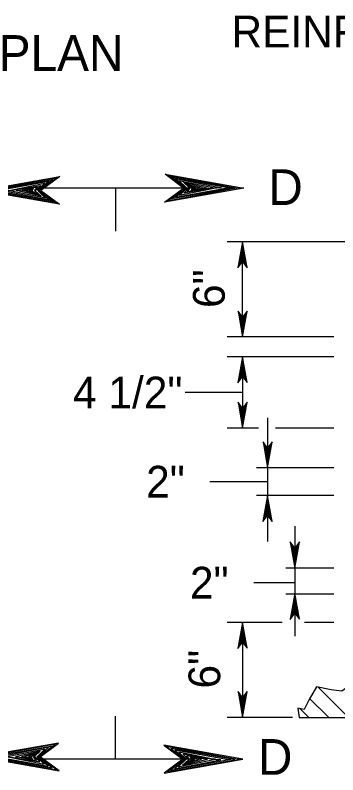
# Model space of a CAD drawing. Extents: x 499866 to 500993, y 499985 to 500645.
# Drawn here: x 500124.8 to 500165.5, y 500455.4 to 500551.1 of the extents above; entities that cross this region are included whole.
import ezdxf

# ---------------------------------------------------------------- set-up
doc = ezdxf.new("R2010")
doc.units = 0
for name, color, linetype in [('2', 7, 'Continuous'), ('24', 7, 'Continuous'), ('5', 7, 'Continuous')]:
    doc.layers.add(name, color=color, linetype=linetype)

msp = doc.modelspace()

# ---------------------------------------------------------------- linework, layer by layer
at = {"layer": '2'}
for p, q in [((500137.466, 500523.851), (500137.466, 500529.295)), ((500137.366, 500462.748), (500137.366, 500457.304))]:
    msp.add_line(p, q, dxfattribs=at)
at = {"layer": '24'}
for points in [[(500153.444, 500522.518), (500152.865, 500519.244), (500153.444, 500520.026), (500154.013, 500519.261), (500153.444, 500522.518), (500153.45, 500522.301), (500152.908, 500519.336), (500153.451, 500520.087), (500153.969, 500519.393), (500153.46, 500522.183), (500153.444, 500522.074), (500152.992, 500519.534), (500153.45, 500520.104), (500153.895, 500519.518), (500153.444, 500522.024), (500153.46, 500521.915), (500153.059, 500519.696), (500153.444, 500520.127), (500153.843, 500519.686), (500153.46, 500521.599), (500153.46, 500521.415), (500153.142, 500519.86), (500153.434, 500520.162), (500153.76, 500519.837), (500153.444, 500521.382), (500153.434, 500521.207), (500153.234, 500520.038), (500153.46, 500520.263), (500153.684, 500520.019), (500153.444, 500521.046), (500153.427, 500520.881), (500153.293, 500520.179), (500153.451, 500520.295), (500153.626, 500520.104), (500153.444, 500520.796), (500153.335, 500520.338), (500153.46, 500520.404), (500153.586, 500520.203), (500153.46, 500520.68), (500153.385, 500520.38), (500153.484, 500520.506), (500153.543, 500520.362), (500153.451, 500520.505), (500153.434, 500520.43)], [(500153.444, 500510.527), (500154.023, 500513.801), (500153.444, 500513.019), (500152.874, 500513.784), (500153.444, 500510.527), (500153.438, 500510.745), (500153.98, 500513.71), (500153.437, 500512.958), (500152.919, 500513.652), (500153.428, 500510.862), (500153.444, 500510.971), (500153.895, 500513.511), (500153.437, 500512.941), (500152.993, 500513.527), (500153.444, 500511.021), (500153.428, 500511.13), (500153.828, 500513.35), (500153.444, 500512.918), (500153.045, 500513.359), (500153.427, 500511.446), (500153.428, 500511.631), (500153.746, 500513.185), (500153.453, 500512.883), (500153.128, 500513.208), (500153.444, 500511.663), (500153.454, 500511.838), (500153.654, 500513.007), (500153.427, 500512.782), (500153.203, 500513.026), (500153.444, 500511.999), (500153.46, 500512.164), (500153.594, 500512.866), (500153.437, 500512.75), (500153.262, 500512.942), (500153.444, 500512.249), (500153.553, 500512.707), (500153.428, 500512.641), (500153.302, 500512.842), (500153.427, 500512.365), (500153.503, 500512.665), (500153.404, 500512.539), (500153.344, 500512.684), (500153.437, 500512.54), (500153.453, 500512.615)], [(500153.444, 500508.029), (500152.865, 500504.755), (500153.444, 500505.537), (500154.013, 500504.772), (500153.444, 500508.029), (500153.45, 500507.812), (500152.908, 500504.846), (500153.451, 500505.598), (500153.969, 500504.904), (500153.46, 500507.694), (500153.444, 500507.585), (500152.992, 500505.045), (500153.45, 500505.615), (500153.895, 500505.029), (500153.444, 500507.535), (500153.46, 500507.427), (500153.059, 500505.206), (500153.444, 500505.638), (500153.843, 500505.198), (500153.46, 500507.11), (500153.46, 500506.926), (500153.142, 500505.371), (500153.434, 500505.673), (500153.76, 500505.348), (500153.444, 500506.893), (500153.434, 500506.718), (500153.234, 500505.549), (500153.46, 500505.774), (500153.684, 500505.53), (500153.444, 500506.557), (500153.427, 500506.392), (500153.293, 500505.69), (500153.451, 500505.806), (500153.626, 500505.615), (500153.444, 500506.307), (500153.335, 500505.849), (500153.46, 500505.915), (500153.586, 500505.714), (500153.46, 500506.192), (500153.385, 500505.891), (500153.484, 500506.017), (500153.543, 500505.873), (500153.451, 500506.016), (500153.434, 500505.941)], [(500153.444, 500499.036), (500154.023, 500502.31), (500153.444, 500501.528), (500152.874, 500502.293), (500153.444, 500499.036), (500153.438, 500499.253), (500153.98, 500502.218), (500153.437, 500501.467), (500152.919, 500502.161), (500153.428, 500499.371), (500153.444, 500499.48), (500153.895, 500502.019), (500153.437, 500501.45), (500152.993, 500502.035), (500153.444, 500499.53), (500153.428, 500499.638), (500153.828, 500501.858), (500153.444, 500501.427), (500153.045, 500501.867), (500153.427, 500499.954), (500153.428, 500500.139), (500153.746, 500501.694), (500153.453, 500501.391), (500153.128, 500501.717), (500153.444, 500500.172), (500153.454, 500500.347), (500153.654, 500501.516), (500153.427, 500501.291), (500153.203, 500501.535), (500153.444, 500500.508), (500153.46, 500500.673), (500153.594, 500501.375), (500153.437, 500501.259), (500153.262, 500501.45), (500153.444, 500500.758), (500153.553, 500501.216), (500153.428, 500501.15), (500153.302, 500501.35), (500153.427, 500500.873), (500153.503, 500501.174), (500153.404, 500501.048), (500153.344, 500501.192), (500153.437, 500501.049), (500153.453, 500501.124)], [(500156.59, 500494.039), (500157.169, 500497.314), (500156.59, 500496.531), (500156.02, 500497.297), (500156.59, 500494.039), (500156.584, 500494.257), (500157.126, 500497.222), (500156.583, 500496.47), (500156.065, 500497.164), (500156.574, 500494.374), (500156.59, 500494.483), (500157.041, 500497.023), (500156.583, 500496.453), (500156.139, 500497.039), (500156.59, 500494.533), (500156.574, 500494.642), (500156.974, 500496.862), (500156.59, 500496.43), (500156.191, 500496.871), (500156.573, 500494.958), (500156.574, 500495.143), (500156.892, 500496.698), (500156.599, 500496.395), (500156.274, 500496.72), (500156.59, 500495.176), (500156.6, 500495.35), (500156.8, 500496.519), (500156.573, 500496.295), (500156.349, 500496.538), (500156.59, 500495.511), (500156.606, 500495.676), (500156.741, 500496.378), (500156.583, 500496.262), (500156.408, 500496.454), (500156.59, 500495.761), (500156.699, 500496.219), (500156.574, 500496.153), (500156.448, 500496.354), (500156.573, 500495.877), (500156.649, 500496.177), (500156.55, 500496.051), (500156.491, 500496.196), (500156.583, 500496.052), (500156.599, 500496.127)], [(500156.59, 500490.542), (500156.011, 500487.268), (500156.59, 500488.051), (500157.159, 500487.285), (500156.59, 500490.542), (500156.596, 500490.325), (500156.054, 500487.36), (500156.597, 500488.112), (500157.115, 500487.417), (500156.606, 500490.208), (500156.59, 500490.098), (500156.138, 500487.559), (500156.596, 500488.129), (500157.041, 500487.543), (500156.59, 500490.049), (500156.606, 500489.94), (500156.205, 500487.72), (500156.59, 500488.152), (500156.989, 500487.711), (500156.606, 500489.624), (500156.606, 500489.439), (500156.288, 500487.885), (500156.58, 500488.187), (500156.906, 500487.861), (500156.59, 500489.406), (500156.58, 500489.231), (500156.38, 500488.062), (500156.606, 500488.287), (500156.83, 500488.043), (500156.59, 500489.071), (500156.573, 500488.906), (500156.439, 500488.204), (500156.597, 500488.32), (500156.772, 500488.128), (500156.59, 500488.82), (500156.481, 500488.362), (500156.606, 500488.428), (500156.732, 500488.228), (500156.606, 500488.705), (500156.531, 500488.405), (500156.63, 500488.531), (500156.689, 500488.386), (500156.597, 500488.53), (500156.58, 500488.454)], [(500153.444, 500474.554), (500152.865, 500471.281), (500153.444, 500472.063), (500154.013, 500471.297), (500153.444, 500474.554), (500153.45, 500474.337), (500152.908, 500471.372), (500153.451, 500472.124), (500153.969, 500471.43), (500153.46, 500474.22), (500153.444, 500474.111), (500152.992, 500471.571), (500153.45, 500472.141), (500153.895, 500471.555), (500153.444, 500474.061), (500153.46, 500473.952), (500153.059, 500471.732), (500153.444, 500472.164), (500153.843, 500471.723), (500153.46, 500473.636), (500153.46, 500473.451), (500153.142, 500471.897), (500153.434, 500472.199), (500153.76, 500471.873), (500153.444, 500473.418), (500153.434, 500473.243), (500153.234, 500472.074), (500153.46, 500472.299), (500153.684, 500472.056), (500153.444, 500473.083), (500153.427, 500472.918), (500153.293, 500472.216), (500153.451, 500472.332), (500153.626, 500472.14), (500153.444, 500472.832), (500153.335, 500472.375), (500153.46, 500472.441), (500153.586, 500472.24), (500153.46, 500472.717), (500153.385, 500472.417), (500153.484, 500472.543), (500153.543, 500472.398), (500153.451, 500472.542), (500153.434, 500472.467)], [(500153.444, 500462.583), (500154.023, 500465.857), (500153.444, 500465.074), (500152.874, 500465.84), (500153.444, 500462.583), (500153.438, 500462.8), (500153.98, 500465.765), (500153.437, 500465.013), (500152.919, 500465.708), (500153.428, 500462.917), (500153.444, 500463.027), (500153.895, 500465.566), (500153.437, 500464.997), (500152.993, 500465.582), (500153.444, 500463.076), (500153.428, 500463.185), (500153.828, 500465.405), (500153.444, 500464.973), (500153.045, 500465.414), (500153.427, 500463.501), (500153.428, 500463.686), (500153.746, 500465.241), (500153.453, 500464.938), (500153.128, 500465.264), (500153.444, 500463.719), (500153.454, 500463.894), (500153.654, 500465.063), (500153.427, 500464.838), (500153.203, 500465.082), (500153.444, 500464.054), (500153.46, 500464.219), (500153.594, 500464.921), (500153.437, 500464.806), (500153.262, 500464.997), (500153.444, 500464.305), (500153.553, 500464.763), (500153.428, 500464.697), (500153.302, 500464.897), (500153.427, 500464.42), (500153.503, 500464.72), (500153.404, 500464.594), (500153.344, 500464.739), (500153.437, 500464.595), (500153.453, 500464.671)]]:
    msp.add_lwpolyline(points, dxfattribs=at)
at = {"layer": '5'}
for p, q in [((500137.466, 500529.295), (500127.474, 500529.295)), ((500147.458, 500529.295), (500137.466, 500529.295)), ((500172.724, 500522.518), (500151.488, 500522.518)), ((500153.444, 500510.527), (500153.444, 500522.518)), ((500164.936, 500510.527), (500151.488, 500510.527)), ((500164.936, 500508.029), (500151.488, 500508.029)), ((500153.444, 500508.029), (500153.444, 500499.036)), ((500153.444, 500503.532), (500146.185, 500503.532)), ((500156.59, 500500.324), (500156.59, 500494.039)), ((500155.433, 500499.036), (500151.488, 500499.036)), ((500164.936, 500499.036), (500157.602, 500499.036)), ((500164.936, 500494.039), (500155.216, 500494.039)), ((500156.59, 500494.039), (500156.59, 500490.542)), ((500156.59, 500492.291), (500149.331, 500492.291)), ((500164.936, 500490.542), (500155.216, 500490.542)), ((500156.59, 500490.542), (500156.59, 500484.769)), ((500160.029, 500486.68), (500160.029, 500481.387)), ((500164.936, 500481.387), (500158.898, 500481.387)), ((500160.029, 500481.387), (500160.029, 500477.739)), ((500160.029, 500479.563), (500154.86, 500479.563)), ((500164.936, 500478.099), (500158.898, 500478.099)), ((500160.029, 500478.099), (500160.029, 500472.831)), ((500158.424, 500474.554), (500151.488, 500474.554)), ((500153.444, 500474.554), (500153.444, 500462.583)), ((500164.936, 500474.554), (500161.233, 500474.554)), ((500162.99, 500466.378), (500166.803, 500462.564)), ((500161.899, 500464.97), (500164.305, 500462.564)), ((500160.672, 500463.698), (500161.807, 500462.564)), ((500159.748, 500462.573), (500151.488, 500462.573)), ((500137.366, 500457.304), (500127.373, 500457.304)), ((500147.358, 500457.304), (500137.366, 500457.304))]:
    msp.add_line(p, q, dxfattribs=at)
for points in [[(500153.59, 500529.295), (500143.619, 500527.532), (500146.001, 500529.295), (500143.67, 500531.03), (500153.59, 500529.295), (500152.928, 500529.314), (500143.898, 500527.663), (500146.187, 500529.316), (500144.073, 500530.893), (500152.571, 500529.344), (500152.238, 500529.295), (500144.503, 500527.92), (500146.239, 500529.315), (500144.454, 500530.669), (500152.087, 500529.294), (500151.756, 500529.344), (500144.993, 500528.124), (500146.309, 500529.294), (500144.967, 500530.511), (500150.792, 500529.345), (500150.23, 500529.344), (500145.495, 500528.375), (500146.416, 500529.267), (500145.425, 500530.259), (500150.13, 500529.295), (500149.597, 500529.264), (500146.037, 500528.655), (500146.721, 500529.346), (500145.98, 500530.028), (500149.108, 500529.295), (500148.605, 500529.245), (500146.468, 500528.836), (500146.82, 500529.316), (500146.237, 500529.849), (500148.345, 500529.294), (500146.951, 500528.964), (500147.152, 500529.344), (500146.54, 500529.726), (500147.994, 500529.346), (500147.079, 500529.116), (500147.462, 500529.418), (500147.023, 500529.598), (500147.461, 500529.316), (500147.231, 500529.267)], [(500120.434, 500528.993), (500130.405, 500530.756), (500128.023, 500528.993), (500130.354, 500527.259), (500120.434, 500528.993)], [(500121.096, 500528.975), (500130.126, 500530.625), (500127.837, 500528.972), (500129.951, 500527.395), (500121.453, 500528.944)], [(500121.785, 500528.993), (500129.521, 500530.368), (500127.785, 500528.973), (500129.57, 500527.619), (500121.937, 500528.994)], [(500122.268, 500528.944), (500129.031, 500530.164), (500127.715, 500528.994), (500129.057, 500527.778), (500123.232, 500528.943)], [(500123.794, 500528.944), (500128.529, 500529.913), (500127.608, 500529.022), (500128.599, 500528.03), (500123.894, 500528.993)], [(500124.427, 500529.024), (500127.987, 500529.634), (500127.302, 500528.942), (500128.044, 500528.26), (500124.916, 500528.993), (500125.419, 500529.044), (500127.556, 500529.452), (500127.204, 500528.972), (500127.787, 500528.44), (500125.679, 500528.995), (500127.073, 500529.325), (500126.872, 500528.944), (500127.484, 500528.562), (500126.03, 500528.942), (500126.945, 500529.172), (500126.562, 500528.871), (500127.001, 500528.691), (500126.563, 500528.972), (500126.793, 500529.022)], [(500160.029, 500481.387), (500160.617, 500484.711), (500160.029, 500483.917), (500159.451, 500484.694), (500160.029, 500481.387), (500160.023, 500481.608), (500160.573, 500484.618), (500160.022, 500483.855), (500159.497, 500484.559), (500160.013, 500481.727), (500160.029, 500481.838), (500160.488, 500484.416), (500160.023, 500483.838), (500159.572, 500484.432), (500160.03, 500481.888), (500160.013, 500481.999), (500160.419, 500484.253), (500160.03, 500483.814), (500159.624, 500484.261), (500160.012, 500482.32), (500160.013, 500482.507), (500160.336, 500484.085), (500160.039, 500483.779), (500159.708, 500484.109), (500160.029, 500482.54), (500160.039, 500482.718), (500160.243, 500483.905), (500160.012, 500483.677), (500159.785, 500483.924), (500160.029, 500482.881), (500160.046, 500483.049), (500160.182, 500483.761), (500160.022, 500483.644), (500159.844, 500483.838), (500160.03, 500483.135), (500160.14, 500483.6), (500160.013, 500483.533), (500159.885, 500483.737), (500160.012, 500483.253), (500160.089, 500483.557), (500159.988, 500483.43), (500159.928, 500483.576), (500160.022, 500483.43), (500160.039, 500483.507)], [(500160.029, 500478.259), (500159.442, 500474.935), (500160.029, 500475.728), (500160.608, 500474.952), (500160.029, 500478.259), (500160.035, 500478.037), (500159.485, 500475.028), (500160.036, 500475.791), (500160.562, 500475.086), (500160.046, 500477.919), (500160.029, 500477.808), (500159.571, 500475.229), (500160.036, 500475.808), (500160.488, 500475.213), (500160.029, 500477.757), (500160.046, 500477.647), (500159.639, 500475.393), (500160.029, 500475.831), (500160.435, 500475.384), (500160.046, 500477.326), (500160.046, 500477.138), (500159.722, 500475.56), (500160.02, 500475.867), (500160.35, 500475.537), (500160.029, 500477.105), (500160.019, 500476.927), (500159.816, 500475.741), (500160.046, 500475.969), (500160.274, 500475.722), (500160.029, 500476.764), (500160.012, 500476.596), (500159.876, 500475.885), (500160.036, 500476.002), (500160.214, 500475.807), (500160.029, 500476.51), (500159.919, 500476.045), (500160.046, 500476.112), (500160.173, 500475.908), (500160.046, 500476.393), (500159.97, 500476.088), (500160.07, 500476.216), (500160.13, 500476.07), (500160.036, 500476.215), (500160.02, 500476.139)], [(500166.835, 500466.517), (500165.966, 500465.899), (500164.615, 500466.065), (500162.769, 500466.421), (500162.298, 500465.635), (500161.826, 500464.85), (500161.198, 500463.593), (500160.413, 500463.75), (500160.59, 500462.573), (500166.803, 500462.564)], [(500120.333, 500457.606), (500130.305, 500455.843), (500127.923, 500457.606), (500130.253, 500459.341), (500120.333, 500457.606)], [(500120.995, 500457.624), (500130.025, 500455.974), (500127.736, 500457.627), (500129.85, 500459.204), (500121.353, 500457.655)], [(500121.685, 500457.606), (500129.42, 500456.231), (500127.685, 500457.626), (500129.469, 500458.98), (500121.837, 500457.605)], [(500122.168, 500457.655), (500128.93, 500456.435), (500127.615, 500457.605), (500128.957, 500458.822), (500123.131, 500457.656)], [(500123.694, 500457.655), (500128.428, 500456.686), (500127.507, 500457.577), (500128.499, 500458.569), (500123.794, 500457.606)], [(500124.326, 500457.575), (500127.887, 500456.966), (500127.202, 500457.657), (500127.944, 500458.339), (500124.816, 500457.606), (500125.318, 500457.555), (500127.456, 500457.147), (500127.104, 500457.627), (500127.686, 500458.159), (500125.578, 500457.604), (500126.972, 500457.274), (500126.771, 500457.655), (500127.383, 500458.037), (500125.929, 500457.657), (500126.844, 500457.427), (500126.461, 500457.728), (500126.901, 500457.908), (500126.463, 500457.627), (500126.692, 500457.577)], [(500153.49, 500457.304), (500143.518, 500459.067), (500145.901, 500457.304), (500143.57, 500455.569), (500153.49, 500457.304), (500152.827, 500457.285), (500143.798, 500458.936), (500146.087, 500457.283), (500143.972, 500455.706), (500152.47, 500457.255), (500152.138, 500457.304), (500144.403, 500458.679), (500146.138, 500457.284), (500144.354, 500455.93), (500151.986, 500457.305), (500151.655, 500457.255), (500144.893, 500458.475), (500146.208, 500457.305), (500144.866, 500456.088), (500150.692, 500457.254), (500150.13, 500457.255), (500145.395, 500458.224), (500146.316, 500457.332), (500145.324, 500456.341), (500150.029, 500457.304), (500149.497, 500457.335), (500145.936, 500457.945), (500146.621, 500457.253), (500145.879, 500456.571), (500149.007, 500457.304), (500148.505, 500457.354), (500146.367, 500457.763), (500146.719, 500457.283), (500146.137, 500456.75), (500148.245, 500457.305), (500146.85, 500457.635), (500147.051, 500457.255), (500146.44, 500456.873), (500147.894, 500457.253), (500146.979, 500457.483), (500147.362, 500457.181), (500146.923, 500457.001), (500147.36, 500457.283), (500147.131, 500457.332)]]:
    msp.add_lwpolyline(points, dxfattribs=at)

# ---------------------------------------------------------------- texts
for s, height, p in [('REINFORCEMENT STEEL', 4, (500152.039, 500547.022)), ('PLAN', 4.5, (500122.701, 500544.067)), ('D', 4.5, (500156.692, 500527.162)), ('4 1/2"', 4, (500132.067, 500501.532)), ('2"', 4, (500141.282, 500490.291)), ('2"', 4, (500146.812, 500477.563)), ('D', 4.5, (500155.38, 500455.351))]:
    msp.add_text(s, height=height, dxfattribs=at).set_placement(p)
for p in [(500151.193, 500514.179), (500150.623, 500466.225)]:
    msp.add_text('6"', height=4, rotation=90, dxfattribs=at).set_placement(p)

doc.saveas('drawing.dxf')
